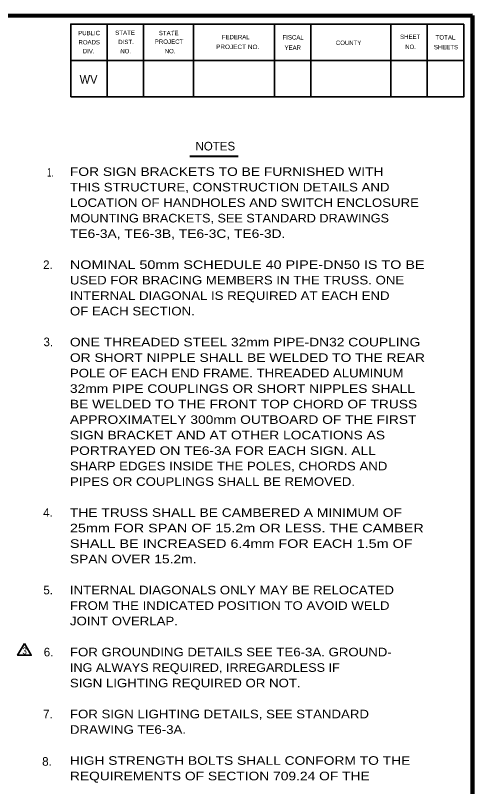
# Model space of a CAD drawing. Extents: x -35 to 821, y -13 to 531.
# Drawn here: x 654.8 to 814.3, y 256.4 to 525.1 of the extents above; entities that cross this region are included whole.
import ezdxf

# ---------------------------------------------------------------- set-up
doc = ezdxf.new("R2010")
doc.units = 0
doc.header["$LTSCALE"] = 0.96
doc.layers.add('1', color=7, linetype='Continuous', lineweight=53)
doc.layers.add('61', color=7, linetype='Continuous', lineweight=35)

msp = doc.modelspace()

# ---------------------------------------------------------------- linework, layer by layer
at = {"layer": '1', "lineweight": 158}
msp.add_line((814.3112, -1.0154), (814.3112, 525.0846), dxfattribs=at)
at = {"layer": '1', "lineweight": 13}
msp.add_line((814.3112, -1.0154), (814.3112, 525.0846), dxfattribs=at)
at = {"layer": '1', "lineweight": 40}
msp.add_line((715.6418, 476.0181), (732.5078, 476.0181), dxfattribs=at)
at = {"layer": '1', "lineweight": 158}
msp.add_lwpolyline([(814.3112, 525.0846), (22.6112, 524.9846), (22.7112, -1.0154)], dxfattribs=at)
at = {"layer": '1', "lineweight": 35}
msp.add_lwpolyline([(657.9461, 306.251), (655.5461, 302.0941), (660.3461, 302.0941)], close=True, dxfattribs=at)
at = {"layer": '61'}
for p, q in [((686.8112, 522.0846), (686.8112, 496.6846)), ((699.5112, 522.0846), (699.5112, 496.6846)), ((716.9112, 522.0846), (716.9112, 496.6846)), ((745.2112, 522.0846), (745.2112, 496.6846)), ((757.9112, 522.0846), (757.9112, 496.6846)), ((785.8112, 522.0846), (785.8112, 496.6846)), ((798.5112, 522.0846), (798.5112, 496.6846)), ((811.2112, 509.3846), (674.1112, 509.3846))]:
    msp.add_line(p, q, dxfattribs=at)
for points in [[(811.2112, 522.0846), (674.1112, 522.0846), (674.1112, 496.6846)], [(811.2112, 522.0846), (811.2112, 496.6846), (674.1112, 496.6846)]]:
    msp.add_lwpolyline(points, dxfattribs=at)

# ---------------------------------------------------------------- texts
at = {"layer": '1'}
for s, height, width, p in [('WV', 3.048, 0.95, (677.2112, 501.2846)), ('1.', 3, 0.65, (665.8814, 468.9489)), ('FOR SIGN BRACKETS TO BE FURNISHED WITH', 3, 1.2, (673.8245, 469.1384)), ('THIS STRUCTURE, CONSTRUCTION DETAILS AND', 3, 1.15, (673.8245, 463.7384)), ('LOCATION OF HANDHOLES AND SWITCH ENCLOSURE', 3, 1.15, (673.8245, 458.3384)), ('MOUNTING BRACKETS, SEE STANDARD DRAWINGS', 3, 1.1, (673.8245, 452.9384)), ('TE6-3A, TE6-3B, TE6-3C, TE6-3D.', 3, 1.2, (673.8245, 447.5384)), ('NOMINAL 50mm SCHEDULE 40 PIPE-DN50 IS TO BE', 3, 1.25, (673.8245, 436.7384)), ('USED FOR BRACING MEMBERS IN THE TRUSS. ONE', 3, 1.15, (673.8245, 431.3384)), ('INTERNAL DIAGONAL IS REQUIRED AT EACH END', 3, 1.15, (673.8245, 425.9384)), ('OF EACH SECTION.', 3, 1.15, (673.8245, 420.5384)), ('ONE THREADED STEEL 32mm PIPE-DN32 COUPLING', 3, 1.2, (673.8245, 409.7384)), ('OR SHORT NIPPLE SHALL BE WELDED TO THE REAR', 3, 1.2, (673.8245, 404.3384)), ('POLE OF EACH END FRAME. THREADED ALUMINUM', 3, 1.15, (673.8245, 398.9384)), ('32mm PIPE COUPLINGS OR SHORT NIPPLES SHALL', 3, 1.2, (673.8245, 393.5384)), ('BE WELDED TO THE FRONT TOP CHORD OF TRUSS', 3, 1.2, (673.8245, 388.1384)), ('APPROXIMATELY 300mm OUTBOARD OF THE FIRST', 3, 1.2, (673.8245, 382.7384)), ('SIGN BRACKET AND AT OTHER LOCATIONS AS', 3, 1.2, (673.8245, 377.3384)), ('PORTRAYED ON TE6-3A FOR EACH SIGN. ALL', 3, 1.2, (673.8245, 371.9384)), ('SHARP EDGES INSIDE THE POLES, CHORDS AND', 3, 1.15, (673.8245, 366.5384)), ('PIPES OR COUPLINGS SHALL BE REMOVED.', 3, 1.15, (673.8245, 361.1384)), ('THE TRUSS SHALL BE CAMBERED A MINIMUM OF', 3, 1.2, (673.8245, 350.3384)), ('25mm FOR SPAN OF 15.2m OR LESS. THE CAMBER', 3, 1.25, (673.8245, 344.9384)), ('SHALL BE INCREASED 6.4mm FOR EACH 1.5m OF', 3, 1.25, (673.8245, 339.5384)), ('SPAN OVER 15.2m.', 3, 1.2, (673.8245, 334.1384)), ('INTERNAL DIAGONALS ONLY MAY BE RELOCATED', 3, 1.15, (673.8245, 323.3384)), ('FROM THE INDICATED POSITION TO AVOID WELD', 3, 1.15, (673.8245, 317.9384)), ('JOINT OVERLAP.', 3, 1.15, (673.8245, 312.5384)), ('3', 2.4, 0.9, (657.2055, 302.4277)), ('FOR GROUNDING DETAILS SEE TE6-3A. GROUND-', 3, 1.15, (673.8245, 301.7384)), ('ING ALWAYS REQUIRED, IRREGARDLESS IF', 3, 1.1, (673.8245, 296.3384)), ('SIGN LIGHTING REQUIRED OR NOT.', 3, 1.15, (673.8245, 290.9384)), ('FOR SIGN LIGHTING DETAILS, SEE STANDARD', 3, 1.15, (673.8245, 280.1384)), ('DRAWING TE6-3A.', 3, 1.15, (673.8245, 274.7384)), ('HIGH STRENGTH BOLTS SHALL CONFORM TO THE', 3, 1.2, (673.8245, 263.9384)), ('REQUIREMENTS OF SECTION 709.24 OF THE', 3, 1.2, (673.8245, 258.5384))]:
    msp.add_text(s, height=height, dxfattribs=dict(at, width=width)).set_placement(p)
for s, p in [('NOTES', (717.6507, 478.0277)), ('2.', (664.4674, 436.6984)), ('3.', (664.6088, 409.823)), ('4.', (664.5023, 350.3637)), ('5.', (664.5615, 323.3419)), ('6.', (664.6943, 301.7278)), ('7.', (664.4744, 280.1755)), ('8.', (664.145, 263.6198))]:
    msp.add_text(s, height=3, dxfattribs=at).set_placement(p)
at = {"layer": '61'}
for s, height, rotation, p in [('PUBLIC', 1.525, 0.033, (676.7112, 518.1846)), ('ROADS', 1.525, 0.124, (676.8112, 514.9846)), ('DIST.', 1.525, 0.056, (690.7112, 515.0846)), ('FEDERAL', 1.523, 0.007, (726.8112, 516.7846)), ('FISCAL', 1.525, 359.942, (748.0112, 516.6846)), ('COUNTY', 1.523, 0.069, (766.6112, 514.7846)), ('SHEET', 1.525, 0.059, (789.0112, 516.8846)), ('DIV.', 1.525, 359.932, (678.3112, 511.8846)), ('YEAR', 1.523, 0.105, (748.7112, 513.0846)), ('SHEETS', 1.523, 359.959, (800.8112, 513.2846))]:
    msp.add_text(s, height=height, rotation=rotation, dxfattribs=at).set_placement(p)
for s, rotation, width, p in [('STATE', 0.059, 1.05, (689.6112, 518.2846)), ('STATE', 0.059, 1.05, (704.8112, 518.1846)), ('PROJECT', 359.908, 1.05, (703.4112, 515.1846)), ('TOTAL', 359.926, 1.05, (801.4112, 516.6846)), ('NO.', 359.852, 0.9, (691.4112, 511.8846)), ('NO.', 0.225, 0.9, (706.9112, 511.8846)), ('PROJECT NO.', 359.922, 1.1, (724.8112, 513.3846)), ('NO.', 359.852, 0.9, (790.8112, 513.3846))]:
    msp.add_text(s, height=1.525, rotation=rotation, dxfattribs=dict(at, width=width)).set_placement(p)

doc.saveas('drawing.dxf')
